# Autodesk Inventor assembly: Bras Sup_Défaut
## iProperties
Shininess: 64.0
Length Units: 11269
Angle Units: 11279
Time Units: 11290
Mass Units: 11283
Length Display Precision: 3
Angle Display Precision: 2
Compacted: True
Created: 2006-11
Part Number: Bras Sup_Défaut
Document SubType Name: Assembly
Designer: profs_sti
Density: 0.0
Volumn: 0.0
Area: 0.0
PropertySet Name: Model Information
Control State: 0
Master: False
Checked Out: False
Author: profs_sti
